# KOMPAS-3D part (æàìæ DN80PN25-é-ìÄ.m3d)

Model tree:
1. Объединить компоненты:1  (labels: СЕНС DN80PN25-В-НО)

Referenced files in D:\Савин\!СЕНСОР\3D для заказчика\!Новый перечень\СЕНС\6. СЕНС-В-НО\DN80\: СЕНС DN80PN25-В-НО.a3d
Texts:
  СЕНС DN80PN25-В-НО
  ООО НПП Сенсор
